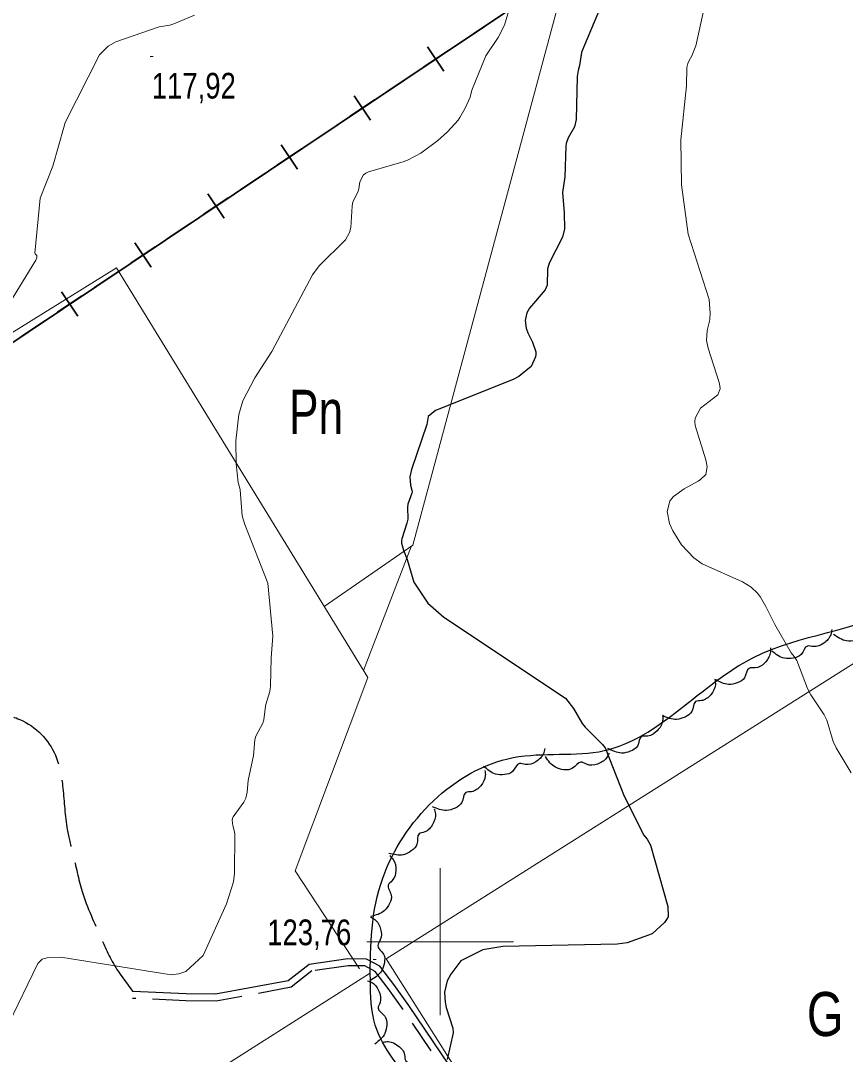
# Model space of a CAD drawing. Extents: x 483843 to 488449, y 4381269 to 4384483.
# Drawn here: x 486857.1 to 487138, y 4382461.7 to 4382813.6 of the extents above; entities that cross this region are included whole.
import ezdxf
from ezdxf.enums import TextEntityAlignment as Align

# ---------------------------------------------------------------- set-up
doc = ezdxf.new("R2010")
doc.units = 0
doc.header["$LTSCALE"] = 3.8
doc.linetypes.add('LONG_DASHED', pattern=[7.5, 6, -1.5])
doc.linetypes.add('MEDIUM_DASHED', pattern=[4.5, 3, -1.5])
for name, color, linetype, lineweight in [('1', 7, 'Continuous', 13), ('27', 7, 'Continuous', 25), ('34', 7, 'Continuous', 35), ('38', 7, 'Continuous', 25), ('51', 7, 'Continuous', 13), ('7', 7, 'Continuous', 13), ('8', 7, 'Continuous', 25), ('9', 7, 'Continuous', 13)]:
    doc.layers.add(name, color=color, linetype=linetype, lineweight=lineweight)
doc.layers.add('31', color=7, linetype='Continuous')

msp = doc.modelspace()

# ---------------------------------------------------------------- linework, layer by layer
at = {"layer": '1'}
for p, q in [((487000, 4382525), (487000, 4382475)), ((486975, 4382500), (487025, 4382500))]:
    msp.add_line(p, q, dxfattribs=at)
at = {"layer": '27'}
for points in [[(486286.37, 4382818.73), (486339.99, 4382829.8), (486391.37, 4382851.5), (486440.09, 4382863.84), (486483.65, 4382864.6), (486530.94, 4382876.91), (486556.13, 4382891.91), (486581.09, 4382903.76), (486654.31, 4382924.49), (486662.47, 4382925.04), (486711.17, 4382931.08), (486727.4, 4382937.04), (486766.91, 4382937.87), (486808.31, 4382909.18), (486821.81, 4382880.51), (486820.67, 4382841.64), (486812.49, 4382812.89), (486799.42, 4382770.69), (486791.78, 4382745.03), (486785, 4382714.29), (486784.58, 4382691.25), (486792.33, 4382675.66), (486812.73, 4382668.89), (486834.8, 4382649.92), (486842.09, 4382627.43), (486847.24, 4382607.13), (486841.07, 4382582.93), (486840.3, 4382544.36), (486820.33, 4382480.87), (486817.63, 4382459.06), (486815.97, 4382420.47), (486812.52, 4382387.85), (486799.99, 4382362.84), (486771.04, 4382337.85), (486733.51, 4382314.2), (486712.72, 4382296.59), (486687.38, 4382263.88), (486690.96, 4382229.15), (486713.22, 4382200.82), (486764.33, 4382192.43), (486778.5, 4382149.68), (486779.01, 4382117.89), (486787.15, 4382072.98), (486813.93, 4382065.66), (486857.54, 4382071.08), (486866.35, 4382080.34), (486893.23, 4382096.95), (486915.85, 4382116.25), (486928.06, 4382127.9), (486936.43, 4382157.7), (486928.1, 4382176.05), (486914.22, 4382205.24), (486902.98, 4382218.81), (486885.61, 4382249.79), (486879.29, 4382279.36), (486884.99, 4382315.26), (486888.52, 4382343.76), (486907.35, 4382375.88), (486922.54, 4382388.35), (486945.58, 4382366.33), (486954.28, 4382323.31), (486963.51, 4382283.6), (486982.52, 4382253.24), (487009.26, 4382225.98), (487037.6, 4382230.32), (487058.96, 4382252.37), (487069.68, 4382284.84), (487065.95, 4382338.17), (487054.24, 4382363.72), (487038.01, 4382386.56), (487027.59, 4382400.37), (487012.06, 4382422.24), (486991.9, 4382450.1), (486977.88, 4382471.56), (486976.21, 4382486.9), (486980.43, 4382521.64), (487024.88, 4382562.69), (487055.81, 4382565.06), (487106.74, 4382596.8), (487155.96, 4382614.11), (487207.74, 4382666.72), (487232.21, 4382676.6), (487267.31, 4382683.94), (487282.71, 4382693.48), (487294.56, 4382707.98), (487340.16, 4382736.84), (487389.67, 4382736.07), (487421.36, 4382716.33), (487454.29, 4382680.57), (487455.44, 4382629.06), (487501.37, 4382598.97)], [(487153.87, 4382613.21), (487153.65, 4382611.45), (487151.42, 4382608.38), (487147.99, 4382607.02), (487145.94, 4382607.08), (487144, 4382604.1), (487141.39, 4382602.65), (487138.37, 4382602.42), (487133.94, 4382604.63)], [(487133.35, 4382606.29), (487133.02, 4382604.54), (487130.6, 4382601.62), (487127.09, 4382600.49), (487125.04, 4382600.68), (487122.92, 4382597.83), (487120.22, 4382596.55), (487117.2, 4382596.51), (487112.91, 4382599.01)], [(487112.44, 4382600.04), (487112.41, 4382598.26), (487110.53, 4382594.97), (487107.27, 4382593.24), (487105.23, 4382593.08), (487103.63, 4382589.9), (487101.19, 4382588.17), (487098.22, 4382587.61), (487093.57, 4382589.32)], [(487093.58, 4382589.3), (487093.71, 4382587.52), (487092.12, 4382584.08), (487089.02, 4382582.08), (487087, 4382581.74), (487085.68, 4382578.44), (487083.4, 4382576.51), (487080.49, 4382575.69), (487075.7, 4382577)], [(487075.74, 4382576.95), (487075.75, 4382575.17), (487073.94, 4382571.84), (487070.72, 4382570.04), (487068.67, 4382569.83), (487067.14, 4382566.63), (487064.74, 4382564.85), (487061.79, 4382564.22), (487057.1, 4382565.84)], [(487035.61, 4382565.75), (487035.17, 4382564.03), (487032.56, 4382561.27), (487028.98, 4382560.36), (487026.96, 4382560.69), (487024.65, 4382557.99), (487021.87, 4382556.89), (487018.86, 4382557.04), (487014.74, 4382559.81)], [(487057.49, 4382564.19), (487056.67, 4382562.61), (487053.53, 4382560.5), (487049.84, 4382560.4), (487047.93, 4382561.17), (487045.08, 4382559.04), (487042.13, 4382558.58), (487039.22, 4382559.4), (487035.82, 4382563.01)], [(487015.23, 4382558.31), (487015.36, 4382556.54), (487013.78, 4382553.09), (487010.68, 4382551.09), (487008.66, 4382550.74), (487007.35, 4382547.44), (487005.07, 4382545.5), (487002.16, 4382544.68), (486997.38, 4382545.98)], [(486997.94, 4382545.3), (486998.37, 4382543.58), (486997.42, 4382539.91), (486994.71, 4382537.39), (486992.78, 4382536.71), (486992.06, 4382533.22), (486990.15, 4382530.92), (486987.43, 4382529.61), (486982.49, 4382530.06)], [(486982.8, 4382529.3), (486983.99, 4382527.99), (486984.89, 4382524.31), (486983.69, 4382520.81), (486982.31, 4382519.29), (486983.32, 4382515.88), (486982.73, 4382512.96), (486980.95, 4382510.51), (486976.38, 4382508.57)], [(486976.24, 4382508.46), (486977.77, 4382507.55), (486979.7, 4382504.29), (486979.59, 4382500.6), (486978.72, 4382498.74), (486980.68, 4382495.78), (486980.98, 4382492.81), (486979.99, 4382489.95), (486976.2, 4382486.76)], [(486975.28, 4382486.71), (486976.9, 4382485.99), (486979.2, 4382482.97), (486979.51, 4382479.29), (486978.86, 4382477.34), (486981.16, 4382474.63), (486981.79, 4382471.71), (486981.15, 4382468.76), (486977.75, 4382465.15)], [(486980.55, 4382465.83), (486982.32, 4382465.99), (486985.8, 4382464.48), (486987.87, 4382461.43), (486988.25, 4382459.41), (486991.58, 4382458.16), (486993.56, 4382455.93), (486994.44, 4382453.04), (486993.24, 4382448.23)]]:
    msp.add_spline(points, degree=3, dxfattribs=at)
at = {"layer": '34'}
for p, q in [((487015.05, 4382811.68), (487006.74, 4382806.12)), ((487001.22, 4382796.4), (486995.66, 4382804.71)), ((487002.59, 4382803.34), (486994.28, 4382797.78)), ((486990.13, 4382795), (486981.82, 4382789.43)), ((486977.67, 4382786.66), (486969.36, 4382781.09)), ((486976.3, 4382779.72), (486970.73, 4382788.03)), ((486965.21, 4382778.31), (486956.9, 4382772.75)), ((486952.75, 4382769.97), (486944.44, 4382764.41)), ((486951.38, 4382763.04), (486945.81, 4382771.35)), ((486940.28, 4382761.63), (486931.97, 4382756.07)), ((486927.83, 4382753.29), (486919.52, 4382747.73)), ((486926.45, 4382746.36), (486920.89, 4382754.67)), ((486915.36, 4382744.95), (486907.05, 4382739.39)), ((486901.53, 4382729.67), (486895.97, 4382737.98)), ((486902.91, 4382736.61), (486894.6, 4382731.05)), ((486890.44, 4382728.27), (486882.13, 4382722.7)), ((486877.98, 4382719.93), (486869.67, 4382714.37)), ((486876.61, 4382712.99), (486871.05, 4382721.3)), ((486865.52, 4382711.58), (486857.21, 4382706.02))]:
    msp.add_line(p, q, dxfattribs=at)
msp.add_lwpolyline([(487676.62, 4383311.4), (487577, 4383232), (487304, 4383028), (487077, 4382869), (487054, 4382844), (487031, 4382851), (487023, 4382817), (486778, 4382653), (486740, 4382634), (486629, 4382532), (486583, 4382537), (486557, 4382471), (486289, 4382313), (486283, 4382292), (486265, 4382283)], dxfattribs=at)
at = {"layer": '38', "linetype": 'MEDIUM_DASHED'}
msp.add_lwpolyline([(487132.61, 4382249.07), (487116.04, 4382275.22), (487084.25, 4382324.31), (487059.46, 4382365.36), (487029.55, 4382412.35), (487022.36, 4382421.09), (487006.5, 4382448.62), (486987.37, 4382476.92), (486982.31, 4382484.1), (486977.9, 4382489.89), (486974.35, 4382491.77), (486968.66, 4382491.78), (486956.3, 4382490.05), (486949.27, 4382484.47), (486923.72, 4382479.74), (486913.38, 4382479.91), (486895.25, 4382480.66)], dxfattribs=at)
at = {"layer": '38'}
msp.add_lwpolyline([(487135.18, 4382249.39), (487118.01, 4382276.49), (487086.24, 4382325.55), (487061.45, 4382366.59), (487031.45, 4382413.72), (487024.29, 4382422.43), (487008.49, 4382449.86), (486989.29, 4382478.25), (486984.2, 4382485.48), (486979.45, 4382491.71), (486974.93, 4382494.11), (486968.5, 4382494.13), (486955.35, 4382492.28), (486948.27, 4382486.66), (486923.52, 4382482.08), (486913.44, 4382482.25), (486895.35, 4382483)], dxfattribs=at)
at = {"layer": '38', "linetype": 'LONG_DASHED'}
msp.add_spline([(486773.89, 4382502.85), (486780.1, 4382507.1), (486783.78, 4382514.38), (486791.93, 4382522.65), (486804.88, 4382534.7), (486820.64, 4382545.07), (486824.67, 4382549.51), (486829.92, 4382560.12), (486837.1, 4382568.29), (486846.6, 4382576.74), (486856.82, 4382575.68), (486868.93, 4382563.48), (486871.49, 4382552.29), (486872.98, 4382538.22), (486874.88, 4382530.01), (486878.07, 4382517.1), (486884.56, 4382501.11), (486888.32, 4382493.24), (486895.35, 4382483)], degree=3, dxfattribs=at)
at = {"layer": '51'}
msp.add_line((486990.27, 4382634.75), (486973.91, 4382592.34), dxfattribs=at)
for points in [[(486960.5, 4382614.18), (486990.67, 4382635.03), (487046.62, 4382843.21), (486975.39, 4382852.9), (486875.9, 4382865.44)], [(487537.56, 4382833.81), (487285.63, 4382686.27), (486981.61, 4382494.14), (487135.5, 4382250.96)], [(486598.64, 4382591.36), (486708.63, 4382625.46), (486758.41, 4382665.73), (486768.75, 4382655.52), (486780.92, 4382661.93), (486889.76, 4382729.45), (486975.33, 4382590.01), (486950.61, 4382524.09), (486972.53, 4382490.72)], [(486758.35, 4382352.97), (486777.31, 4382364.39), (486906.28, 4382444.86), (486975.94, 4382489.22)]]:
    msp.add_lwpolyline(points, dxfattribs=at)
at = {"layer": '7'}
for p, q in [((486901.26, 4382801.48), (486902.26, 4382801.48)), ((486977.14, 4382493.9), (486978.14, 4382493.9))]:
    msp.add_line(p, q, dxfattribs=at)
at = {"layer": '8'}
for points in [[(487061.76, 4382835.38), (487048.26, 4382803.13), (487048.17, 4382802.79), (487047.49, 4382798.34), (487046.98, 4382796.64), (487046.64, 4382794.57), (487046.34, 4382779.97)], [(487046.34, 4382779.97), (487045.75, 4382777.48), (487043.61, 4382773.79), (487042.88, 4382771.76), (487042.75, 4382770.94), (487042.42, 4382760.48), (487041.59, 4382755.14), (487042.21, 4382748.21), (487042.29, 4382742.71), (487041.68, 4382739.88), (487037.16, 4382731.09), (487036.53, 4382729.15), (487036.42, 4382723.53), (487036.12, 4382722.74), (487035.69, 4382721.93), (487030.41, 4382715.75), (487029.49, 4382714.18), (487028.88, 4382711.57), (487029.29, 4382708.95), (487029.84, 4382707.35), (487031.39, 4382704.21), (487032.51, 4382700.91), (487032.53, 4382700.01), (487032.43, 4382699.11), (487031.03, 4382695.87), (487026.77, 4382692.45), (487024.86, 4382691.43), (486998.34, 4382680.94), (486995.94, 4382678.86), (486995.45, 4382676.14), (486990.24, 4382660.85), (486989.69, 4382658.29), (486989.85, 4382655.44), (486990.38, 4382653.71), (486990.39, 4382653.22), (486990.35, 4382652.73), (486989, 4382649.04), (486988.82, 4382647.97), (486988.93, 4382643.83), (486988.67, 4382642.5), (486986.88, 4382637.17), (486986.83, 4382636.45), (486986.84, 4382635.75), (486987.49, 4382633.31), (486988.71, 4382630.2), (486990.99, 4382622.4), (486995.82, 4382615.28), (487001.28, 4382610.54), (487042.62, 4382582.88), (487045.4, 4382579.45), (487048.32, 4382574.32), (487049.36, 4382573), (487055.26, 4382567.18), (487056.18, 4382566), (487062.6, 4382549.57), (487063.27, 4382548.49), (487069.28, 4382536.4), (487070.5, 4382534.89), (487071.63, 4382532.89), (487077.54, 4382511.94), (487077.59, 4382508.5), (487077.12, 4382507.51), (487076.44, 4382506.49), (487072.22, 4382502.68), (487063.69, 4382499.67), (487060.29, 4382499.17), (487021.37, 4382498.39), (487014.48, 4382497.27), (487007.03, 4382493.53), (487003.59, 4382488.95), (487002.39, 4382486.63), (487001.49, 4382482.85), (487001.67, 4382479.41), (487001.98, 4382477.58), (487004.25, 4382470.52), (487004.4, 4382469), (487002.32, 4382459.85)]]:
    msp.add_lwpolyline(points, dxfattribs=at)
at = {"layer": '9'}
for points in [[(487092.68, 4382830.79), (487087.03, 4382805.1), (487085.73, 4382801.7), (487084.7, 4382799.87), (487084.31, 4382798.99), (487083.96, 4382797.67), (487083.88, 4382791.46), (487081.97, 4382773.01), (487082.16, 4382757.69), (487084.39, 4382740.91), (487091.62, 4382718.66), (487091.97, 4382714.03), (487091.83, 4382711.93), (487091.73, 4382711.3), (487090.91, 4382708.15), (487090.73, 4382704.7), (487091.23, 4382702.09), (487095.04, 4382690.47), (487095.25, 4382689.31), (487095.33, 4382688.32), (487094.55, 4382686.2), (487088.68, 4382681.69), (487086.83, 4382678.31), (487086.72, 4382677.09), (487086.78, 4382675.73), (487090.43, 4382664.07), (487090.87, 4382661.75), (487090.47, 4382659.11), (487088.62, 4382657.36), (487087.87, 4382656.83), (487083.1, 4382654.18), (487079.43, 4382651.64), (487078.73, 4382650.82), (487078.18, 4382649.96), (487077.35, 4382646.44), (487078.14, 4382642.38), (487079.19, 4382639.93), (487082.2, 4382635.16), (487086.43, 4382630.68), (487089.23, 4382628.65), (487102.98, 4382622.51), (487105.95, 4382620.71), (487108.02, 4382618.69), (487109.1, 4382617.27), (487110.95, 4382614.17), (487113.93, 4382607.96), (487119.47, 4382598.38), (487120.54, 4382597.1), (487121.44, 4382595.74), (487125.1, 4382586.18), (487126.23, 4382584.02), (487130.8, 4382577.3), (487131.7, 4382575.43), (487133.84, 4382568.2), (487134.83, 4382566), (487140, 4382557.55)], [(486936.81, 4382568.72), (486937.2, 4382570.04), (486939.58, 4382574.44), (486939.98, 4382575.59), (486940.48, 4382580.16), (486940.61, 4382580.72), (486942.01, 4382585.21), (486942.22, 4382586.96), (486942.43, 4382596.7), (486943.01, 4382604.04), (486941.32, 4382622.08), (486933.4, 4382642.06), (486932.57, 4382645.05), (486931.86, 4382653.88), (486931.75, 4382654.46), (486931.23, 4382656.36), (486930.55, 4382662.69), (486930.44, 4382670.58), (486931.44, 4382679.57), (486932.83, 4382684.21), (486936.86, 4382691.97), (486942.6, 4382700.94), (486956.46, 4382727.07), (486958.77, 4382730.11), (486967.75, 4382739.05), (486969.12, 4382741.54), (486969.57, 4382743.25), (486969.97, 4382750.44), (486970.24, 4382751.91), (486971.92, 4382755.25), (486972.25, 4382756.34), (486972.58, 4382758.74), (486973.9, 4382761.13), (486974.68, 4382761.69), (486975.63, 4382762.2), (486987.69, 4382765.64), (486989.05, 4382766.19), (486993.4, 4382768.51), (486999.17, 4382772.79), (487002.52, 4382775.8), (487006.07, 4382779.78), (487006.7, 4382780.65), (487008.55, 4382783.82), (487010.18, 4382787.55), (487010.81, 4382790), (487015.53, 4382801.66), (487019.77, 4382807.95), (487021.84, 4382812.15), (487024.11, 4382819.8)], [(486916.27, 4382815.48), (486909.32, 4382812.55), (486907.9, 4382812.12), (486904.23, 4382811.56), (486889.54, 4382806.48), (486886.96, 4382804.96), (486883.93, 4382802), (486872.32, 4382778.99), (486871.91, 4382777.67), (486868.11, 4382764.07), (486863.71, 4382753.14), (486861.99, 4382734.5), (486862.09, 4382734.25), (486862.21, 4382734.08), (486862.57, 4382733.7), (486862.6, 4382732.9), (486862.24, 4382732.12), (486853.34, 4382717.38)], [(486852.89, 4382471.68), (486862.92, 4382492.62), (486864.46, 4382494.05), (486865.24, 4382494.31), (486866.17, 4382494.5), (486870.82, 4382494.69), (486908.33, 4382488.68), (486910.99, 4382489.08), (486913.34, 4382489.83), (486919.25, 4382495.28), (486927.16, 4382512.87), (486929.59, 4382520.43), (486929.93, 4382523.17), (486930.07, 4382536.58), (486929.98, 4382537.4), (486929.34, 4382539.58), (486929.11, 4382541.37), (486929.27, 4382541.95), (486929.53, 4382542.55), (486933.16, 4382547.57), (486933.8, 4382548.86), (486934.24, 4382550.97), (486934.64, 4382554.84), (486936.41, 4382563.41), (486936.81, 4382568.72)]]:
    msp.add_lwpolyline(points, dxfattribs=at)

# ---------------------------------------------------------------- texts
at = {"layer": '31'}
for s, width, p in [('Pn', 0.75, (486957.72, 4382672.94)), ('G', 0.8, (487131.12, 4382467.87))]:
    msp.add_text(s, height=15, dxfattribs=dict(at, width=width)).set_placement(p, align=Align.CENTER)
at = {"layer": '7', "width": 0.8}
for s, p in [('117,92', (486901.76, 4382787.11)), ('123,76', (486941.08, 4382498.81))]:
    msp.add_text(s, height=8.75, dxfattribs=at).set_placement(p)

doc.saveas('drawing.dxf')
